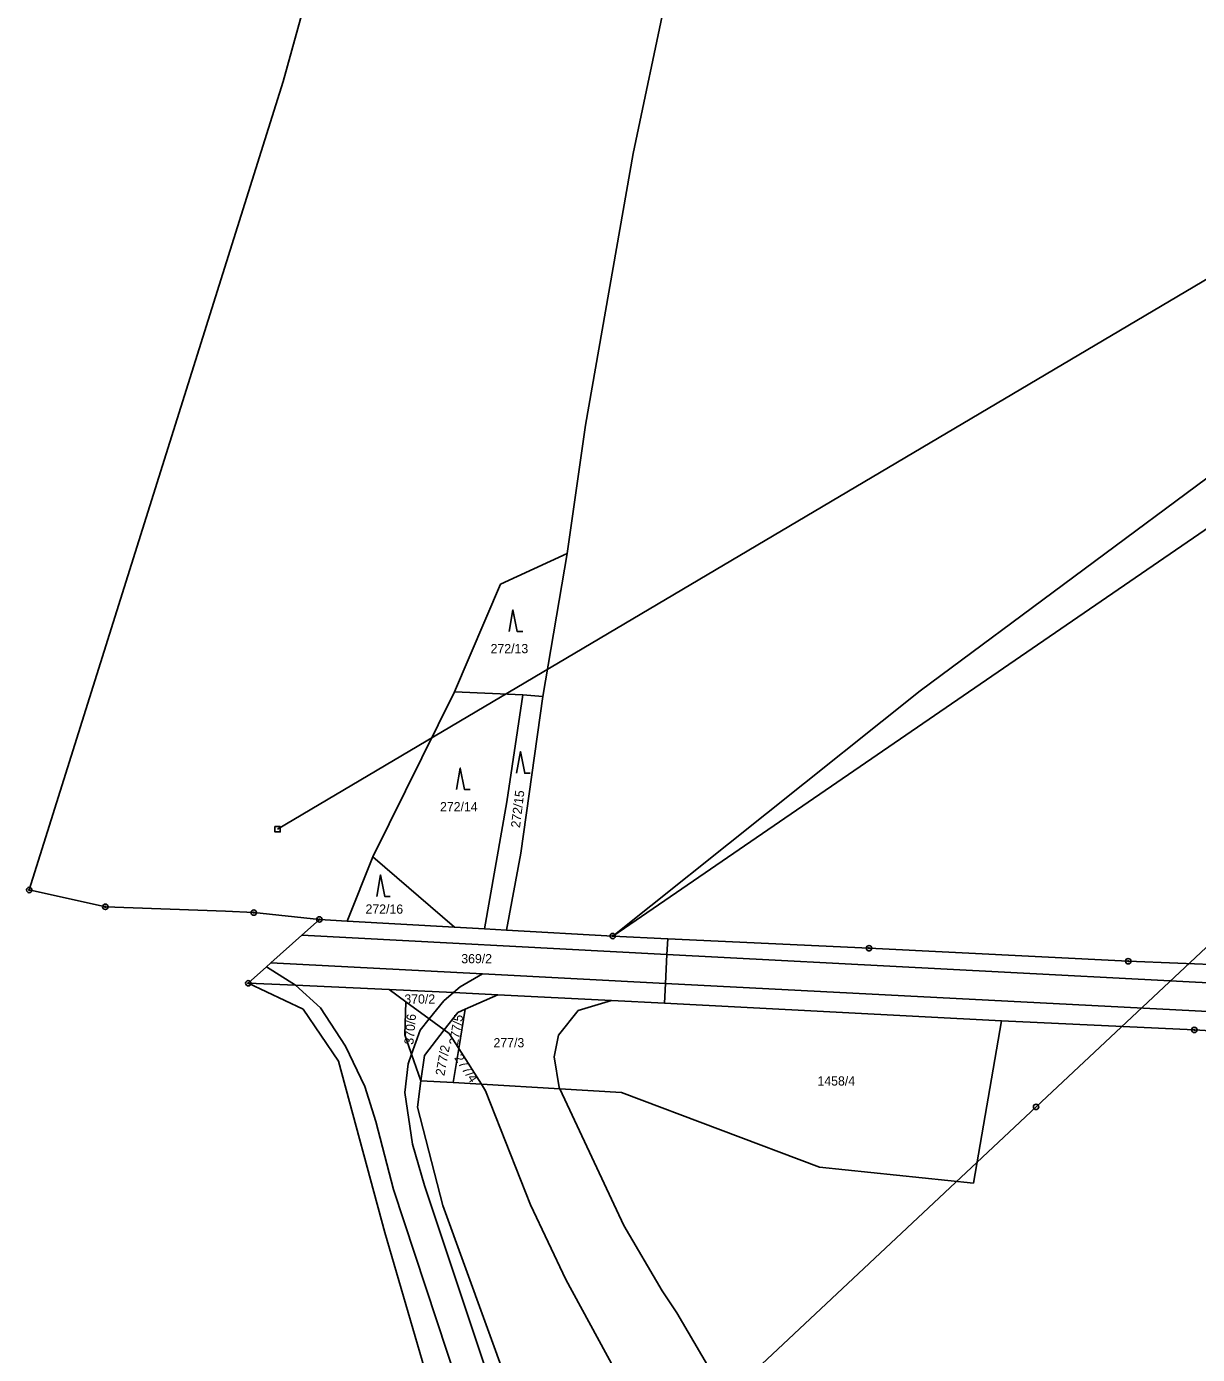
# Model space of a CAD drawing. Extents: x -762263 to -760336, y -1154405 to -1152076.
# Drawn here: x -762262.5 to -762046, y -1152561.1 to -1152315.5 of the extents above; entities that cross this region are included whole.
import ezdxf

# ---------------------------------------------------------------- set-up
doc = ezdxf.new("R2010")
doc.units = 0
for name, color, linetype in [('Vrstva 1', 7, 'Continuous'), ('Vrstva 12', 7, 'Continuous'), ('Vrstva 13', 7, 'Continuous'), ('Vrstva 18', 7, 'Continuous'), ('Vrstva 24', 7, 'Continuous'), ('Vrstva 25', 7, 'Continuous'), ('Vrstva 26', 7, 'Continuous'), ('Vrstva 4', 7, 'Continuous'), ('Vrstva 6', 7, 'Continuous')]:
    doc.layers.add(name, color=color, linetype=linetype)

msp = doc.modelspace()

# ---------------------------------------------------------------- linework, layer by layer
at = {"layer": 'Vrstva 1'}
for p, q in [((-761964.87, -1152353.92), (-762154.13, -1152483.71)), ((-762208.38, -1152480.64), (-762203.24, -1152480.93)), ((-762203.24, -1152480.93), (-762183.37, -1152482.06)), ((-762183.37, -1152482.06), (-762177.86, -1152482.37)), ((-762177.86, -1152482.37), (-762173.81, -1152482.6)), ((-762173.81, -1152482.6), (-762154.13, -1152483.71)), ((-762154.13, -1152483.71), (-762143.94, -1152484.2)), ((-762144.1, -1152487.11), (-762143.94, -1152484.2)), ((-762143.94, -1152484.2), (-762106.73, -1152485.96)), ((-762144.38, -1152492.47), (-762144.1, -1152487.11)), ((-762058.8, -1152488.37), (-762106.73, -1152485.96)), ((-762030.63, -1152489.47), (-762058.8, -1152488.37)), ((-762212.8, -1152492.82), (-762221.54, -1152492.44)), ((-762195.51, -1152493.57), (-762212.8, -1152492.82)), ((-762183.59, -1152494.16), (-762195.51, -1152493.57)), ((-762192.38, -1152495.87), (-762195.51, -1152493.57)), ((-762175.41, -1152494.56), (-762183.59, -1152494.16)), ((-762175.41, -1152494.56), (-762181.45, -1152497.23)), ((-762154.39, -1152495.63), (-762175.41, -1152494.56)), ((-762144.58, -1152496.12), (-762144.38, -1152492.47)), ((-762188.06, -1152499.03), (-762192.38, -1152495.87)), ((-762181.45, -1152497.23), (-762182.8, -1152497.83)), ((-762181.45, -1152497.23), (-762182.62, -1152504.53)), ((-762160.51, -1152497.45), (-762154.39, -1152495.63)), ((-762154.39, -1152495.63), (-762144.58, -1152496.12)), ((-762082.24, -1152499.4), (-762144.58, -1152496.12)), ((-762188.06, -1152499.03), (-762185.3, -1152501.06)), ((-762182.8, -1152497.83), (-762185.3, -1152501.06)), ((-762164.15, -1152502.07), (-762160.51, -1152497.45)), ((-762087.41, -1152529.39), (-762082.24, -1152499.4)), ((-762082.24, -1152499.4), (-762046.58, -1152501.07)), ((-762185.3, -1152501.06), (-762188.97, -1152505.78)), ((-762185.3, -1152501.06), (-762184.4, -1152501.72)), ((-762182.62, -1152504.53), (-762184.4, -1152501.72)), ((-762164.94, -1152506.08), (-762164.15, -1152502.07)), ((-762018, -1152502.73), (-762046.58, -1152501.07)), ((-762182.62, -1152504.53), (-762183.62, -1152510.82)), ((-762182.62, -1152504.53), (-762178.42, -1152511.12)), ((-762189.61, -1152510.47), (-762188.97, -1152505.78)), ((-762164.04, -1152511.71), (-762164.94, -1152506.08)), ((-762189.61, -1152510.47), (-762190.27, -1152515.33)), ((-762183.62, -1152510.82), (-762189.61, -1152510.47)), ((-762183.62, -1152510.82), (-762178.42, -1152511.12)), ((-762178.42, -1152511.12), (-762177.65, -1152512.34)), ((-762178.42, -1152511.12), (-762163.92, -1152511.96)), ((-762164.04, -1152511.71), (-762163.92, -1152511.96)), ((-762163.92, -1152511.96), (-762152.52, -1152512.62)), ((-762163.92, -1152511.96), (-762152.1, -1152537.24)), ((-762177.65, -1152512.34), (-762169.34, -1152533.43)), ((-762115.89, -1152526.45), (-762152.52, -1152512.62)), ((-762185.55, -1152533.53), (-762190.27, -1152515.33)), ((-762087.41, -1152529.39), (-762115.89, -1152526.45)), ((-762172.17, -1152570.43), (-762185.55, -1152533.53)), ((-762169.34, -1152533.43), (-762162.8, -1152547.22)), ((-762145, -1152549.3), (-762152.1, -1152537.24)), ((-762162.8, -1152547.22), (-762152.37, -1152566.39)), ((-762142.3, -1152553.42), (-762145, -1152549.3)), ((-762119.86, -1152591.38), (-762142.3, -1152553.42))]:
    msp.add_line(p, q, dxfattribs=at)
at = {"layer": 'Vrstva 12'}
for p, q in [((-761992.86, -1152331.75), (-762216.11, -1152463.96)), ((-761979.67, -1152425.13), (-762075.84, -1152515.3)), ((-762075.84, -1152515.3), (-762153.67, -1152588.32))]:
    msp.add_line(p, q, dxfattribs=at)
at = {"layer": 'Vrstva 13'}
for p, q in [((-762215.11, -1152325.64), (-762192.1, -1152243.03)), ((-762262.04, -1152475.19), (-762215.11, -1152325.64)), ((-762262.04, -1152475.19), (-762247.97, -1152478.3)), ((-762247.97, -1152478.3), (-762225.73, -1152479.11)), ((-762225.73, -1152479.11), (-762220.51, -1152479.37)), ((-762220.51, -1152479.37), (-762208.38, -1152480.64)), ((-762211.62, -1152483.55), (-762208.38, -1152480.64)), ((-762217.34, -1152488.68), (-762211.62, -1152483.55)), ((-762221.54, -1152492.44), (-762218.14, -1152489.4)), ((-762218.14, -1152489.4), (-762217.34, -1152488.68)), ((-762211.36, -1152497.26), (-762221.54, -1152492.44)), ((-762204.84, -1152506.84), (-762211.36, -1152497.26)), ((-762196.29, -1152538.57), (-762204.84, -1152506.84)), ((-762186.41, -1152572.39), (-762196.29, -1152538.57))]:
    msp.add_line(p, q, dxfattribs=at)
at = {"layer": 'Vrstva 24'}
for centre, radius in [((-762262.04, -1152475.19), 0.5), ((-762262.04, -1152475.19), 0.1), ((-762247.97, -1152478.3), 0.5), ((-762247.97, -1152478.3), 0.1), ((-762220.51, -1152479.37), 0.5), ((-762220.51, -1152479.37), 0.1), ((-762208.38, -1152480.64), 0.5), ((-762208.38, -1152480.64), 0.1), ((-762154.13, -1152483.71), 0.5), ((-762154.13, -1152483.71), 0.1), ((-762106.73, -1152485.96), 0.5), ((-762106.73, -1152485.96), 0.1), ((-762058.8, -1152488.37), 0.5), ((-762058.8, -1152488.37), 0.1), ((-762221.54, -1152492.44), 0.5), ((-762221.54, -1152492.44), 0.1), ((-762046.58, -1152501.07), 0.5), ((-762046.58, -1152501.07), 0.1)]:
    msp.add_circle(centre, radius, dxfattribs=at)
at = {"layer": 'Vrstva 25'}
for points in [[(-762173.28, -1152427.39), (-762172.58, -1152423.39), (-762171.78, -1152427.39), (-762170.78, -1152427.39)], [(-762171.92, -1152453.59), (-762171.22, -1152449.59), (-762170.42, -1152453.59), (-762169.42, -1152453.59)], [(-762183.02, -1152456.63), (-762182.32, -1152452.63), (-762181.52, -1152456.63), (-762180.52, -1152456.63)], [(-762197.78, -1152476.4), (-762197.08, -1152472.4), (-762196.28, -1152476.4), (-762195.28, -1152476.4)]]:
    msp.add_lwpolyline(points, dxfattribs=at)
at = {"layer": 'Vrstva 26'}
msp.add_lwpolyline([(-762216.61, -1152463.46), (-762215.61, -1152463.46), (-762215.61, -1152464.46), (-762216.61, -1152464.46)], close=True, dxfattribs=at)
msp.add_circle((-762075.84, -1152515.3), 0.5, dxfattribs=at)
at = {"layer": 'Vrstva 4'}
for p, q in [((-762144.1, -1152487.11), (-762211.62, -1152483.55)), ((-761927.69, -1152498.52), (-762144.1, -1152487.11)), ((-762212.8, -1152492.82), (-762218.14, -1152489.4)), ((-762178.24, -1152490.71), (-762217.34, -1152488.68)), ((-762182.38, -1152493.12), (-762178.24, -1152490.71)), ((-762178.24, -1152490.71), (-762144.38, -1152492.47)), ((-762208.18, -1152497), (-762212.8, -1152492.82)), ((-762185.4, -1152495.7), (-762183.59, -1152494.16)), ((-762183.59, -1152494.16), (-762182.38, -1152493.12)), ((-762144.38, -1152492.47), (-761928.48, -1152503.7)), ((-762203.53, -1152504.1), (-762208.18, -1152497)), ((-762188.06, -1152499.03), (-762185.4, -1152495.7)), ((-762189.74, -1152501.13), (-762188.06, -1152499.03)), ((-762191.34, -1152505.54), (-762189.74, -1152501.13)), ((-762200, -1152511.56), (-762203.53, -1152504.1)), ((-762191.99, -1152507.34), (-762191.34, -1152505.54)), ((-762192.59, -1152512.67), (-762191.99, -1152507.34)), ((-762197.93, -1152517.99), (-762200, -1152511.56)), ((-762191.16, -1152522.18), (-762192.59, -1152512.67)), ((-762194.68, -1152530.57), (-762197.93, -1152517.99)), ((-762188.97, -1152529.85), (-762191.16, -1152522.18)), ((-762173.44, -1152594.91), (-762194.68, -1152530.57)), ((-762167.51, -1152594.17), (-762188.97, -1152529.85))]:
    msp.add_line(p, q, dxfattribs=at)
at = {"layer": 'Vrstva 6'}
for p, q in [((-762141.59, -1152297.35), (-762150.38, -1152338.95)), ((-761938, -1152320.01), (-762097.25, -1152438.36)), ((-762150.38, -1152338.95), (-762159.15, -1152389.2)), ((-762159.15, -1152389.2), (-762162.59, -1152412.95)), ((-762162.59, -1152412.95), (-762174.89, -1152418.64)), ((-762162.59, -1152412.95), (-762167.07, -1152439.4)), ((-762174.89, -1152418.64), (-762183.41, -1152438.56)), ((-762154.13, -1152483.71), (-762097.25, -1152438.36)), ((-762183.41, -1152438.56), (-762198.48, -1152469.06)), ((-762183.41, -1152438.56), (-762170.78, -1152439.12)), ((-762173.71, -1152458.87), (-762170.78, -1152439.12)), ((-762171.12, -1152468.4), (-762167.07, -1152439.4)), ((-762170.78, -1152439.12), (-762167.07, -1152439.4)), ((-762177.86, -1152482.37), (-762173.71, -1152458.87)), ((-762198.48, -1152469.06), (-762203.24, -1152480.93)), ((-762198.48, -1152469.06), (-762183.37, -1152482.06)), ((-762173.81, -1152482.6), (-762171.12, -1152468.4)), ((-762192.38, -1152495.87), (-762192.59, -1152501.98)), ((-762191.34, -1152505.54), (-762192.59, -1152501.98)), ((-762189.61, -1152510.47), (-762191.34, -1152505.54))]:
    msp.add_line(p, q, dxfattribs=at)

# ---------------------------------------------------------------- texts
at = {"layer": 'Vrstva 18'}
for s, p in [('272/13', (-762176.719, -1152431.39)), ('272/14', (-762186.072, -1152460.63)), ('369/2', (-762182.143, -1152488.74)), ('370/2', (-762192.67, -1152496.2)), ('277/3', (-762176.183, -1152504.29)), ('1458/4', (-762116.268, -1152511.36))]:
    msp.add_text(s, height=1.7, dxfattribs=at).set_placement(p)
for s, rotation, p in [('272/15', 83.02158, (-762171.297, -1152463.759)), ('272/16', 359.81749, (-762199.852, -1152479.558)), ('370/6', 84.85505, (-762191.004, -1152503.853)), ('277/5', 79.75572, (-762182.778, -1152503.998)), ('277/2', 79.46925, (-762185.277, -1152509.647)), ('277/4', 303.09467, (-762183.501, -1152506.239))]:
    msp.add_text(s, height=1.7, rotation=rotation, dxfattribs=at).set_placement(p)

doc.saveas('drawing.dxf')
